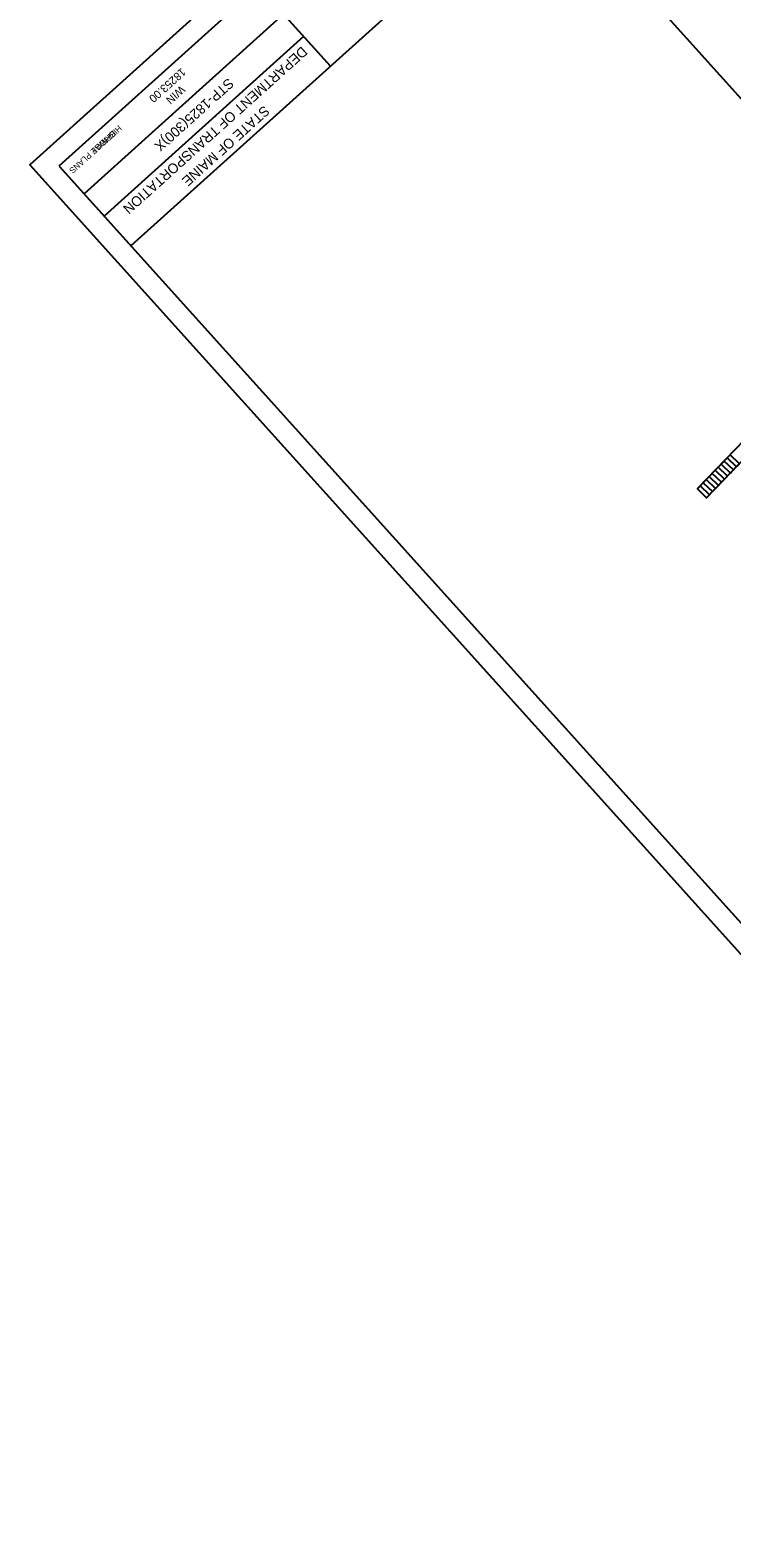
# Model space of a CAD drawing. Extents: x 1111534 to 1112511, y 616515 to 617559.
# Drawn here: x 1111534 to 1111860, y 616515 to 617209 of the extents above; entities that cross this region are included whole.
import ezdxf

# ---------------------------------------------------------------- set-up
doc = ezdxf.new("R2010")
doc.units = 0
for name, color, linetype in [('BORDER', 7, 'Continuous'), ('BRIDGE_TITLE', 7, 'Continuous'), ('CLIPS', 7, 'Continuous'), ('HIGHWAY_TITLE', 7, 'Continuous'), ('PLOT BOUNDARY', 7, 'Continuous'), ('SIGNS TRAFFIC', 7, 'Continuous')]:
    doc.layers.add(name, color=color, linetype=linetype)

msp = doc.modelspace()

# ---------------------------------------------------------------- linework, layer by layer
at = {"layer": 'BORDER'}
for p, q in [((1111937.23, 617496.95), (1111547.08, 617145.66)), ((1111970.69, 617459.79), (1111580.54, 617108.5)), ((1111673.46, 617192.17), (1111640.01, 617229.33)), ((1111651.63, 617216.4), (1111558.74, 617132.76)), ((1111660.98, 617206.01), (1111568.09, 617122.37)), ((1111547.09, 617145.67), (1112082.4, 616551.15))]:
    msp.add_line(p, q, dxfattribs=at)
at = {"layer": 'CLIPS'}
msp.add_lwpolyline([(1112472.55, 616902.44), (1111970.7, 617459.8), (1111771.54, 617280.48), (1112273.39, 616723.12)], close=True, dxfattribs=at)
at = {"layer": 'PLOT BOUNDARY'}
msp.add_lwpolyline([(1112510.99, 616882.61), (1111942.23, 617514.28), (1111533.5, 617146.26), (1112102.26, 616514.59)], close=True, dxfattribs=at)
at = {"layer": 'SIGNS TRAFFIC'}
for p, q in [((1111870.58, 617022.74), (1111844.26, 616995.33)), ((1111848.59, 616991.17), (1111874.91, 617018.58))]:
    msp.add_line(p, q, dxfattribs=at)
for points in [[(1111858.29, 617001.27), (1111853.95, 617005.43), (1111852.57, 617003.98), (1111856.9, 616999.83)], [(1111861.06, 617004.16), (1111856.73, 617008.31), (1111855.34, 617006.87), (1111859.67, 617002.71)], [(1111863.83, 617007.04), (1111859.5, 617011.2), (1111858.11, 617009.75), (1111862.44, 617005.6)], [(1111852.75, 616995.5), (1111848.41, 616999.65), (1111847.03, 616998.21), (1111851.36, 616994.06)], [(1111855.52, 616998.39), (1111851.18, 617002.54), (1111849.8, 617001.1), (1111854.13, 616996.94)], [(1111849.98, 616992.62), (1111845.65, 616996.77), (1111844.28, 616995.34), (1111848.59, 616991.17), (1111848.6, 616991.19)]]:
    msp.add_lwpolyline(points, close=True, dxfattribs=at)

# ---------------------------------------------------------------- texts
at = {"layer": 'BORDER'}
for s, height, p in [('DEPARTMENT OF TRANSPORTATION', 4.6588, (1111660.09, 617201.7)), ('18253.00', 3.726, (1111604.08, 617191.57)), ('STP-1825(300)X', 4.6588, (1111625.86, 617186.93)), ('WIN', 3.726, (1111603.71, 617183.44)), ('STATE OF MAINE', 4.6588, (1111642.52, 617174.1))]:
    msp.add_text(s, height=height, rotation=222, dxfattribs=at).set_placement(p)
at = {"layer": 'BRIDGE_TITLE'}
msp.add_text('BRIDGE PLANS', height=2.795, rotation=222, dxfattribs=at).set_placement((1111572.12, 617162.53))
at = {"layer": 'HIGHWAY_TITLE'}
msp.add_text('HIGHWAY PLANS', height=2.795, rotation=222, dxfattribs=at).set_placement((1111574.75, 617164.9))

doc.saveas('drawing.dxf')
